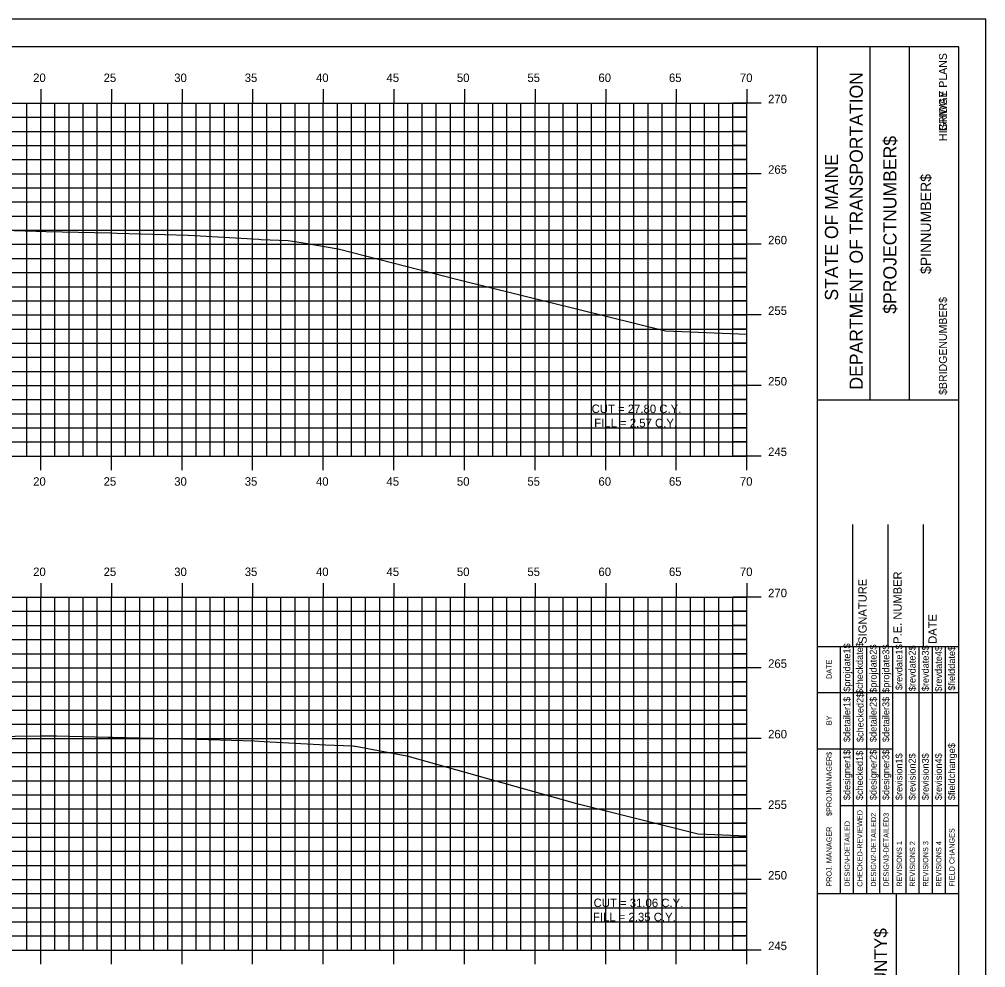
# Model space of a CAD drawing. Extents: x 1160718 to 1173142, y 616002 to 617630.
# Drawn here: x 1171089.7 to 1171158.1, y 616656.7 to 616723.9 of the extents above; entities that cross this region are included whole.
import ezdxf

# ---------------------------------------------------------------- set-up
doc = ezdxf.new("R2010")
doc.units = 0
for name, color, linetype in [('ANNOTATION', 7, 'Continuous'), ('BORDER', 7, 'Continuous'), ('BRIDGE_TITLE', 7, 'Continuous'), ('H_V ANNOTATION', 7, 'Continuous'), ('HIGHWAY_TITLE', 7, 'Continuous'), ('MAJOR', 7, 'Continuous'), ('MINOR', 7, 'Continuous'), ('PLOT BOUNDARY', 7, 'Continuous'), ('S_Roadway_Centerline', 7, 'Continuous')]:
    doc.layers.add(name, color=color, linetype=linetype)

msp = doc.modelspace()

# ---------------------------------------------------------------- linework, layer by layer
at = {"layer": 'BORDER'}
for p, q in [((1171156.177, 616721.928), (1170996.177, 616721.928)), ((1171146.177, 616616.931), (1171146.177, 616721.931)), ((1171149.905, 616696.925), (1171149.905, 616721.925)), ((1171152.701, 616696.925), (1171152.701, 616721.925)), ((1171156.177, 616616.931), (1171156.177, 616721.931)), ((1171146.178, 616696.923), (1171156.177, 616696.923)), ((1171148.677, 616679.431), (1171148.677, 616688.079)), ((1171151.177, 616679.431), (1171151.177, 616688.079)), ((1171153.677, 616679.431), (1171153.677, 616688.079)), ((1171146.177, 616679.431), (1171156.177, 616679.431)), ((1171146.177, 616661.931), (1171156.177, 616661.931)), ((1171151.768, 616626.931), (1171151.768, 616661.931))]:
    msp.add_line(p, q, dxfattribs=at)
for points in [[(1171147.792, 616676.181), (1171147.792, 616679.431)], [(1171148.724, 616661.934), (1171148.724, 616679.431)], [(1171149.656, 616679.431), (1171149.656, 616661.934)], [(1171150.588, 616661.934), (1171150.588, 616679.431)], [(1171151.519, 616661.934), (1171151.519, 616679.431)], [(1171152.451, 616661.934), (1171152.451, 616679.431)], [(1171153.383, 616661.934), (1171153.383, 616679.431)], [(1171154.314, 616661.934), (1171154.314, 616679.431)], [(1171155.246, 616661.934), (1171155.246, 616679.431)], [(1171147.793, 616661.934), (1171147.793, 616678.725)], [(1171146.177, 616676.181), (1171156.177, 616676.181)], [(1171146.177, 616672.181), (1171147.793, 616672.181)], [(1171147.792, 616672.181), (1171151.518, 616672.181)], [(1171147.792, 616668.181), (1171156.177, 616668.181)]]:
    msp.add_lwpolyline(points, dxfattribs=at)
at = {"layer": 'MAJOR'}
for p, q in [((1171091.177, 616718.93), (1171091.177, 616717.928)), ((1171096.177, 616718.93), (1171096.177, 616717.928)), ((1171101.177, 616718.93), (1171101.177, 616717.928)), ((1171106.177, 616718.93), (1171106.177, 616717.928)), ((1171111.177, 616718.93), (1171111.177, 616717.928)), ((1171116.177, 616718.93), (1171116.177, 616717.928)), ((1171121.177, 616718.93), (1171121.177, 616717.928)), ((1171126.177, 616718.93), (1171126.177, 616717.928)), ((1171131.177, 616718.93), (1171131.177, 616717.928)), ((1171136.177, 616718.93), (1171136.177, 616717.928)), ((1171141.177, 616718.93), (1171141.177, 616717.928)), ((1171001.177, 616717.928), (1171141.177, 616717.928)), ((1171001.177, 616717.928), (1171141.177, 616717.928)), ((1171091.177, 616692.928), (1171091.177, 616717.928)), ((1171096.177, 616692.928), (1171096.177, 616717.928)), ((1171101.177, 616692.928), (1171101.177, 616717.928)), ((1171106.177, 616692.928), (1171106.177, 616717.928)), ((1171111.177, 616692.928), (1171111.177, 616717.928)), ((1171116.177, 616692.928), (1171116.177, 616717.928)), ((1171121.177, 616692.928), (1171121.177, 616717.928)), ((1171126.177, 616692.928), (1171126.177, 616717.928)), ((1171131.177, 616692.928), (1171131.177, 616717.928)), ((1171136.177, 616692.928), (1171136.177, 616717.928)), ((1171142.179, 616717.928), (1171140.175, 616717.928)), ((1171141.177, 616692.928), (1171141.177, 616717.928)), ((1171141.177, 616692.928), (1171141.177, 616717.928)), ((1171001.177, 616712.928), (1171141.177, 616712.928)), ((1171142.179, 616712.928), (1171140.175, 616712.928)), ((1171001.177, 616707.928), (1171141.177, 616707.928)), ((1171142.179, 616707.928), (1171140.175, 616707.928)), ((1171001.177, 616702.928), (1171141.177, 616702.928)), ((1171142.179, 616702.928), (1171140.175, 616702.928)), ((1171001.177, 616697.928), (1171141.177, 616697.928)), ((1171142.179, 616697.928), (1171140.175, 616697.928)), ((1171001.177, 616692.928), (1171141.177, 616692.928)), ((1171001.177, 616692.928), (1171141.177, 616692.928)), ((1171091.177, 616691.926), (1171091.177, 616692.928)), ((1171096.177, 616691.926), (1171096.177, 616692.928)), ((1171101.177, 616691.926), (1171101.177, 616692.928)), ((1171106.177, 616691.926), (1171106.177, 616692.928)), ((1171111.177, 616691.926), (1171111.177, 616692.928)), ((1171116.177, 616691.926), (1171116.177, 616692.928)), ((1171121.177, 616691.926), (1171121.177, 616692.928)), ((1171126.177, 616691.926), (1171126.177, 616692.928)), ((1171131.177, 616691.926), (1171131.177, 616692.928)), ((1171136.177, 616691.926), (1171136.177, 616692.928)), ((1171142.179, 616692.928), (1171140.175, 616692.928)), ((1171141.177, 616691.926), (1171141.177, 616692.928)), ((1171091.177, 616683.93), (1171091.177, 616682.928)), ((1171096.177, 616683.93), (1171096.177, 616682.928)), ((1171101.177, 616683.93), (1171101.177, 616682.928)), ((1171106.177, 616683.93), (1171106.177, 616682.928)), ((1171111.177, 616683.93), (1171111.177, 616682.928)), ((1171116.177, 616683.93), (1171116.177, 616682.928)), ((1171121.177, 616683.93), (1171121.177, 616682.928)), ((1171126.177, 616683.93), (1171126.177, 616682.928)), ((1171131.177, 616683.93), (1171131.177, 616682.928)), ((1171136.177, 616683.93), (1171136.177, 616682.928)), ((1171141.177, 616683.93), (1171141.177, 616682.928)), ((1171001.177, 616682.928), (1171141.177, 616682.928)), ((1171001.177, 616682.928), (1171141.177, 616682.928)), ((1171091.177, 616657.928), (1171091.177, 616682.928)), ((1171096.177, 616657.928), (1171096.177, 616682.928)), ((1171101.177, 616657.928), (1171101.177, 616682.928)), ((1171106.177, 616657.928), (1171106.177, 616682.928)), ((1171111.177, 616657.928), (1171111.177, 616682.928)), ((1171116.177, 616657.928), (1171116.177, 616682.928)), ((1171121.177, 616657.928), (1171121.177, 616682.928)), ((1171126.177, 616657.928), (1171126.177, 616682.928)), ((1171131.177, 616657.928), (1171131.177, 616682.928)), ((1171136.177, 616657.928), (1171136.177, 616682.928)), ((1171142.179, 616682.928), (1171140.175, 616682.928)), ((1171141.177, 616657.928), (1171141.177, 616682.928)), ((1171141.177, 616657.928), (1171141.177, 616682.928)), ((1171001.177, 616677.928), (1171141.177, 616677.928)), ((1171142.179, 616677.928), (1171140.175, 616677.928)), ((1171001.177, 616672.928), (1171141.177, 616672.928)), ((1171142.179, 616672.928), (1171140.175, 616672.928)), ((1171001.177, 616667.928), (1171141.177, 616667.928)), ((1171142.179, 616667.928), (1171140.175, 616667.928)), ((1171001.177, 616662.928), (1171141.177, 616662.928)), ((1171142.179, 616662.928), (1171140.175, 616662.928)), ((1171001.177, 616657.928), (1171141.177, 616657.928)), ((1171001.177, 616657.928), (1171141.177, 616657.928)), ((1171091.177, 616656.926), (1171091.177, 616657.928)), ((1171096.177, 616656.926), (1171096.177, 616657.928)), ((1171101.177, 616656.926), (1171101.177, 616657.928)), ((1171106.177, 616656.926), (1171106.177, 616657.928)), ((1171111.177, 616656.926), (1171111.177, 616657.928)), ((1171116.177, 616656.926), (1171116.177, 616657.928)), ((1171121.177, 616656.926), (1171121.177, 616657.928)), ((1171126.177, 616656.926), (1171126.177, 616657.928)), ((1171131.177, 616656.926), (1171131.177, 616657.928)), ((1171136.177, 616656.926), (1171136.177, 616657.928)), ((1171142.179, 616657.928), (1171140.175, 616657.928)), ((1171141.177, 616656.926), (1171141.177, 616657.928))]:
    msp.add_line(p, q, dxfattribs=at)
at = {"layer": 'MINOR'}
for p, q in [((1171090.177, 616692.928), (1171090.177, 616717.928)), ((1171092.177, 616692.928), (1171092.177, 616717.928)), ((1171093.177, 616692.928), (1171093.177, 616717.928)), ((1171094.177, 616692.928), (1171094.177, 616717.928)), ((1171095.177, 616692.928), (1171095.177, 616717.928)), ((1171097.177, 616692.928), (1171097.177, 616717.928)), ((1171098.177, 616692.928), (1171098.177, 616717.928)), ((1171099.177, 616692.928), (1171099.177, 616717.928)), ((1171100.177, 616692.928), (1171100.177, 616717.928)), ((1171102.177, 616692.928), (1171102.177, 616717.928)), ((1171103.177, 616692.928), (1171103.177, 616717.928)), ((1171104.177, 616692.928), (1171104.177, 616717.928)), ((1171105.177, 616692.928), (1171105.177, 616717.928)), ((1171107.177, 616692.928), (1171107.177, 616717.928)), ((1171108.177, 616692.928), (1171108.177, 616717.928)), ((1171109.177, 616692.928), (1171109.177, 616717.928)), ((1171110.177, 616692.928), (1171110.177, 616717.928)), ((1171112.177, 616692.928), (1171112.177, 616717.928)), ((1171113.177, 616692.928), (1171113.177, 616717.928)), ((1171114.177, 616692.928), (1171114.177, 616717.928)), ((1171115.177, 616692.928), (1171115.177, 616717.928)), ((1171117.177, 616692.928), (1171117.177, 616717.928)), ((1171118.177, 616692.928), (1171118.177, 616717.928)), ((1171119.177, 616692.928), (1171119.177, 616717.928)), ((1171120.177, 616692.928), (1171120.177, 616717.928)), ((1171122.177, 616692.928), (1171122.177, 616717.928)), ((1171123.177, 616692.928), (1171123.177, 616717.928)), ((1171124.177, 616692.928), (1171124.177, 616717.928)), ((1171125.177, 616692.928), (1171125.177, 616717.928)), ((1171127.177, 616692.928), (1171127.177, 616717.928)), ((1171128.177, 616692.928), (1171128.177, 616717.928)), ((1171129.177, 616692.928), (1171129.177, 616717.928)), ((1171130.177, 616692.928), (1171130.177, 616717.928)), ((1171132.177, 616692.928), (1171132.177, 616717.928)), ((1171133.177, 616692.928), (1171133.177, 616717.928)), ((1171134.177, 616692.928), (1171134.177, 616717.928)), ((1171135.177, 616692.928), (1171135.177, 616717.928)), ((1171137.177, 616692.928), (1171137.177, 616717.928)), ((1171138.177, 616692.928), (1171138.177, 616717.928)), ((1171139.177, 616692.928), (1171139.177, 616717.928)), ((1171140.177, 616692.928), (1171140.177, 616717.928)), ((1171001.177, 616716.928), (1171141.177, 616716.928)), ((1171141.177, 616716.928), (1171140.175, 616716.928)), ((1171001.177, 616715.928), (1171141.177, 616715.928)), ((1171141.177, 616715.928), (1171140.175, 616715.928)), ((1171001.177, 616714.928), (1171141.177, 616714.928)), ((1171141.177, 616714.928), (1171140.175, 616714.928)), ((1171001.177, 616713.928), (1171141.177, 616713.928)), ((1171141.177, 616713.928), (1171140.175, 616713.928)), ((1171001.177, 616711.928), (1171141.177, 616711.928)), ((1171141.177, 616711.928), (1171140.175, 616711.928)), ((1171001.177, 616710.928), (1171141.177, 616710.928)), ((1171141.177, 616710.928), (1171140.175, 616710.928)), ((1171001.177, 616709.928), (1171141.177, 616709.928)), ((1171141.177, 616709.928), (1171140.175, 616709.928)), ((1171001.177, 616708.928), (1171141.177, 616708.928)), ((1171141.177, 616708.928), (1171140.175, 616708.928)), ((1171001.177, 616706.928), (1171141.177, 616706.928)), ((1171141.177, 616706.928), (1171140.175, 616706.928)), ((1171001.177, 616705.928), (1171141.177, 616705.928)), ((1171141.177, 616705.928), (1171140.175, 616705.928)), ((1171001.177, 616704.928), (1171141.177, 616704.928)), ((1171141.177, 616704.928), (1171140.175, 616704.928)), ((1171001.177, 616703.928), (1171141.177, 616703.928)), ((1171141.177, 616703.928), (1171140.175, 616703.928)), ((1171001.177, 616701.928), (1171141.177, 616701.928)), ((1171141.177, 616701.928), (1171140.175, 616701.928)), ((1171001.177, 616700.928), (1171141.177, 616700.928)), ((1171141.177, 616700.928), (1171140.175, 616700.928)), ((1171001.177, 616699.928), (1171141.177, 616699.928)), ((1171141.177, 616699.928), (1171140.175, 616699.928)), ((1171001.177, 616698.928), (1171141.177, 616698.928)), ((1171141.177, 616698.928), (1171140.175, 616698.928)), ((1171001.177, 616696.928), (1171141.177, 616696.928)), ((1171141.177, 616696.928), (1171140.175, 616696.928)), ((1171001.177, 616695.928), (1171141.177, 616695.928)), ((1171141.177, 616695.928), (1171140.175, 616695.928)), ((1171001.177, 616694.928), (1171141.177, 616694.928)), ((1171141.177, 616694.928), (1171140.175, 616694.928)), ((1171001.177, 616693.928), (1171141.177, 616693.928)), ((1171141.177, 616693.928), (1171140.175, 616693.928)), ((1171090.177, 616657.928), (1171090.177, 616682.928)), ((1171092.177, 616657.928), (1171092.177, 616682.928)), ((1171093.177, 616657.928), (1171093.177, 616682.928)), ((1171094.177, 616657.928), (1171094.177, 616682.928)), ((1171095.177, 616657.928), (1171095.177, 616682.928)), ((1171097.177, 616657.928), (1171097.177, 616682.928)), ((1171098.177, 616657.928), (1171098.177, 616682.928)), ((1171099.177, 616657.928), (1171099.177, 616682.928)), ((1171100.177, 616657.928), (1171100.177, 616682.928)), ((1171102.177, 616657.928), (1171102.177, 616682.928)), ((1171103.177, 616657.928), (1171103.177, 616682.928)), ((1171104.177, 616657.928), (1171104.177, 616682.928)), ((1171105.177, 616657.928), (1171105.177, 616682.928)), ((1171107.177, 616657.928), (1171107.177, 616682.928)), ((1171108.177, 616657.928), (1171108.177, 616682.928)), ((1171109.177, 616657.928), (1171109.177, 616682.928)), ((1171110.177, 616657.928), (1171110.177, 616682.928)), ((1171112.177, 616657.928), (1171112.177, 616682.928)), ((1171113.177, 616657.928), (1171113.177, 616682.928)), ((1171114.177, 616657.928), (1171114.177, 616682.928)), ((1171115.177, 616657.928), (1171115.177, 616682.928)), ((1171117.177, 616657.928), (1171117.177, 616682.928)), ((1171118.177, 616657.928), (1171118.177, 616682.928)), ((1171119.177, 616657.928), (1171119.177, 616682.928)), ((1171120.177, 616657.928), (1171120.177, 616682.928)), ((1171122.177, 616657.928), (1171122.177, 616682.928)), ((1171123.177, 616657.928), (1171123.177, 616682.928)), ((1171124.177, 616657.928), (1171124.177, 616682.928)), ((1171125.177, 616657.928), (1171125.177, 616682.928)), ((1171127.177, 616657.928), (1171127.177, 616682.928)), ((1171128.177, 616657.928), (1171128.177, 616682.928)), ((1171129.177, 616657.928), (1171129.177, 616682.928)), ((1171130.177, 616657.928), (1171130.177, 616682.928)), ((1171132.177, 616657.928), (1171132.177, 616682.928)), ((1171133.177, 616657.928), (1171133.177, 616682.928)), ((1171134.177, 616657.928), (1171134.177, 616682.928)), ((1171135.177, 616657.928), (1171135.177, 616682.928)), ((1171137.177, 616657.928), (1171137.177, 616682.928)), ((1171138.177, 616657.928), (1171138.177, 616682.928)), ((1171139.177, 616657.928), (1171139.177, 616682.928)), ((1171140.177, 616657.928), (1171140.177, 616682.928)), ((1171001.177, 616681.928), (1171141.177, 616681.928)), ((1171141.177, 616681.928), (1171140.175, 616681.928)), ((1171001.177, 616680.928), (1171141.177, 616680.928)), ((1171141.177, 616680.928), (1171140.175, 616680.928)), ((1171001.177, 616679.928), (1171141.177, 616679.928)), ((1171141.177, 616679.928), (1171140.175, 616679.928)), ((1171001.177, 616678.928), (1171141.177, 616678.928)), ((1171141.177, 616678.928), (1171140.175, 616678.928)), ((1171001.177, 616676.928), (1171141.177, 616676.928)), ((1171141.177, 616676.928), (1171140.175, 616676.928)), ((1171001.177, 616675.928), (1171141.177, 616675.928)), ((1171141.177, 616675.928), (1171140.175, 616675.928)), ((1171001.177, 616674.928), (1171141.177, 616674.928)), ((1171141.177, 616674.928), (1171140.175, 616674.928)), ((1171001.177, 616673.928), (1171141.177, 616673.928)), ((1171141.177, 616673.928), (1171140.175, 616673.928)), ((1171001.177, 616671.928), (1171141.177, 616671.928)), ((1171141.177, 616671.928), (1171140.175, 616671.928)), ((1171001.177, 616670.928), (1171141.177, 616670.928)), ((1171141.177, 616670.928), (1171140.175, 616670.928)), ((1171001.177, 616669.928), (1171141.177, 616669.928)), ((1171141.177, 616669.928), (1171140.175, 616669.928)), ((1171001.177, 616668.928), (1171141.177, 616668.928)), ((1171141.177, 616668.928), (1171140.175, 616668.928)), ((1171001.177, 616666.928), (1171141.177, 616666.928)), ((1171141.177, 616666.928), (1171140.175, 616666.928)), ((1171001.177, 616665.928), (1171141.177, 616665.928)), ((1171141.177, 616665.928), (1171140.175, 616665.928)), ((1171001.177, 616664.928), (1171141.177, 616664.928)), ((1171141.177, 616664.928), (1171140.175, 616664.928)), ((1171001.177, 616663.928), (1171141.177, 616663.928)), ((1171141.177, 616663.928), (1171140.175, 616663.928)), ((1171001.177, 616661.928), (1171141.177, 616661.928)), ((1171141.177, 616661.928), (1171140.175, 616661.928)), ((1171001.177, 616660.928), (1171141.177, 616660.928)), ((1171141.177, 616660.928), (1171140.175, 616660.928)), ((1171001.177, 616659.928), (1171141.177, 616659.928)), ((1171141.177, 616659.928), (1171140.175, 616659.928)), ((1171001.177, 616658.928), (1171141.177, 616658.928)), ((1171141.177, 616658.928), (1171140.175, 616658.928))]:
    msp.add_line(p, q, dxfattribs=at)
at = {"layer": 'PLOT BOUNDARY'}
msp.add_lwpolyline([(1170988.084, 616613.869), (1171158.084, 616613.869), (1171158.084, 616723.869), (1170988.084, 616723.869)], close=True, dxfattribs=at)
at = {"layer": 'S_Roadway_Centerline'}
for points in [[(1171087.685, 616708.946), (1171090.852, 616708.865), (1171091.567, 616708.845), (1171096.1, 616708.74), (1171096.586, 616708.729), (1171101.601, 616708.58), (1171101.605, 616708.58), (1171101.641, 616708.578), (1171106.624, 616708.287), (1171106.791, 616708.28), (1171108.683, 616708.208), (1171109.602, 616708.055), (1171112.224, 616707.615), (1171120.806, 616705.414), (1171135.401, 616701.802), (1171141.177, 616701.56)], [(1171087.467, 616673.05), (1171091.232, 616673.113), (1171092.104, 616673.112), (1171092.296, 616673.111), (1171095.941, 616673.021), (1171096.257, 616673.013), (1171100.116, 616672.923), (1171101.281, 616672.896), (1171101.411, 616672.893), (1171106.306, 616672.755), (1171106.993, 616672.716), (1171111.331, 616672.463), (1171113.242, 616672.392), (1171113.41, 616672.385), (1171113.453, 616672.377), (1171117.105, 616671.691), (1171128.952, 616668.351), (1171137.729, 616666.171), (1171141.177, 616666.017)]]:
    msp.add_lwpolyline(points, dxfattribs=at)

# ---------------------------------------------------------------- texts
at = {"layer": 'ANNOTATION'}
for s, p in [('CUT = 27.80 C.Y.', (1171130.178, 616695.978)), ('FILL = 2.57 C.Y.', (1171130.364, 616694.976)), ('CUT = 31.06 C.Y.', (1171130.318, 616660.978)), ('FILL = 2.35 C.Y.', (1171130.273, 616659.976))]:
    msp.add_text(s, height=0.6, rotation=359.92408, dxfattribs=at).set_placement(p)
at = {"layer": 'BORDER'}
for s, height, p in [('DEPARTMENT OF TRANSPORTATION', 0.93176, (1171149.384, 616697.634)), ('$PROJECTNUMBER$', 0.93176, (1171151.769, 616703.008)), ('STATE OF MAINE', 0.93176, (1171147.632, 616703.94)), ('$PINNUMBER$', 0.74527, (1171154.214, 616705.825)), ('P.E. NUMBER', 0.59055, (1171152.138, 616679.624)), ('SIGNATURE', 0.5906, (1171149.657, 616679.624)), ('DATE', 0.5906, (1171154.618, 616679.624)), ('$projdate1$', 0.48455, (1171148.5, 616676.232)), ('$checkdate$', 0.48455, (1171149.394, 616676.074)), ('$projdate2$', 0.48455, (1171150.363, 616676.153)), ('$projdate3$', 0.48455, (1171151.258, 616676.153)), ('$revdate1$', 0.4845, (1171152.189, 616676.35)), ('$revdate2$', 0.4845, (1171153.121, 616676.271)), ('$revdate3$', 0.4845, (1171154.053, 616676.271)), ('$revdate4$', 0.4845, (1171154.984, 616676.232)), ('$fielddate$', 0.48455, (1171155.916, 616676.31)), ('DATE', 0.3714, (1171147.181, 616677.137)), ('$checked2$', 0.4845, (1171149.432, 616672.667)), ('$detailer1$', 0.48455, (1171148.5, 616672.667)), ('$detailer2$', 0.48455, (1171150.363, 616672.667)), ('$detailer3$', 0.48455, (1171151.258, 616672.667)), ('BY', 0.3714, (1171147.181, 616673.866)), ('$designer1$', 0.48455, (1171148.5, 616668.555)), ('$checked1$', 0.4845, (1171149.394, 616668.555)), ('$designer2$', 0.48455, (1171150.363, 616668.555)), ('$designer3$', 0.48455, (1171151.258, 616668.555)), ('$fieldchange$', 0.48455, (1171155.916, 616668.555)), ('$PROJMANAGER$', 0.37275, (1171147.181, 616667.426)), ('$revision1$', 0.48455, (1171152.189, 616668.555)), ('$revision2$', 0.48455, (1171153.121, 616668.555)), ('$revision3$', 0.48455, (1171154.053, 616668.555)), ('$revision4$', 0.48455, (1171154.984, 616668.555)), ('CHECKED-REVIEWED', 0.37275, (1171149.358, 616662.419)), ('DESIGN2-DETAILED2', 0.37275, (1171150.327, 616662.419)), ('DESIGN3-DETAILED3', 0.37275, (1171151.221, 616662.419)), ('DESIGN-DETAILED', 0.37275, (1171148.463, 616662.419)), ('PROJ. MANAGER', 0.37275, (1171147.181, 616662.419)), ('FIELD CHANGES', 0.37275, (1171155.88, 616662.419)), ('REVISIONS 1', 0.37275, (1171152.153, 616662.419)), ('REVISIONS 2', 0.37275, (1171153.085, 616662.419)), ('REVISIONS 3', 0.37275, (1171154.016, 616662.419)), ('REVISIONS 4', 0.37275, (1171154.948, 616662.419))]:
    msp.add_text(s, height=height, rotation=90, dxfattribs=at).set_placement(p)
at = {"layer": 'BRIDGE_TITLE'}
for s, height, p in [('BRIDGE PLANS', 0.55901, (1171155.335, 616715.953)), ('$BRIDGENUMBER$', 0.55901, (1171155.335, 616697.259)), ('$COUNTY$', 0.9072, (1171151.097, 616653.011))]:
    msp.add_text(s, height=height, rotation=90, dxfattribs=at).set_placement(p)
at = {"layer": 'H_V ANNOTATION'}
for s, p in [('20', (1171090.631, 616719.428)), ('25', (1171095.623, 616719.428)), ('30', (1171100.625, 616719.428)), ('35', (1171105.617, 616719.428)), ('40', (1171110.663, 616719.428)), ('45', (1171115.655, 616719.428)), ('50', (1171120.641, 616719.428)), ('55', (1171125.633, 616719.428)), ('60', (1171130.663, 616719.428)), ('65', (1171135.655, 616719.428)), ('70', (1171140.679, 616719.428)), ('270', (1171142.677, 616717.928)), ('265', (1171142.677, 616712.928)), ('260', (1171142.677, 616707.928)), ('255', (1171142.677, 616702.928)), ('250', (1171142.677, 616697.928)), ('245', (1171142.677, 616692.928)), ('20', (1171090.631, 616690.828)), ('25', (1171095.623, 616690.828)), ('30', (1171100.625, 616690.828)), ('35', (1171105.617, 616690.828)), ('40', (1171110.663, 616690.828)), ('45', (1171115.655, 616690.828)), ('50', (1171120.641, 616690.828)), ('55', (1171125.633, 616690.828)), ('60', (1171130.663, 616690.828)), ('65', (1171135.655, 616690.828)), ('70', (1171140.679, 616690.828)), ('20', (1171090.631, 616684.428)), ('25', (1171095.623, 616684.428)), ('30', (1171100.625, 616684.428)), ('35', (1171105.617, 616684.428)), ('40', (1171110.663, 616684.428)), ('45', (1171115.655, 616684.428)), ('50', (1171120.641, 616684.428)), ('55', (1171125.633, 616684.428)), ('60', (1171130.663, 616684.428)), ('65', (1171135.655, 616684.428)), ('70', (1171140.679, 616684.428)), ('270', (1171142.677, 616682.928)), ('265', (1171142.677, 616677.928)), ('260', (1171142.677, 616672.928)), ('255', (1171142.677, 616667.928)), ('250', (1171142.677, 616662.928)), ('245', (1171142.677, 616657.928))]:
    msp.add_text(s, height=0.6, dxfattribs=at).set_placement(p)
at = {"layer": 'HIGHWAY_TITLE'}
msp.add_text('HIGHWAY PLANS', height=0.55901, rotation=90, dxfattribs=at).set_placement((1171155.335, 616715.244))

doc.saveas('drawing.dxf')
